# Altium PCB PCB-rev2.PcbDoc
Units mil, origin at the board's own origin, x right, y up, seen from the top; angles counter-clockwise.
Board outline 1995 x 2300 mil, 2 copper layers (Top Layer, Bottom Layer); 24 components, 81 nets, 313 pads, 170 vias.
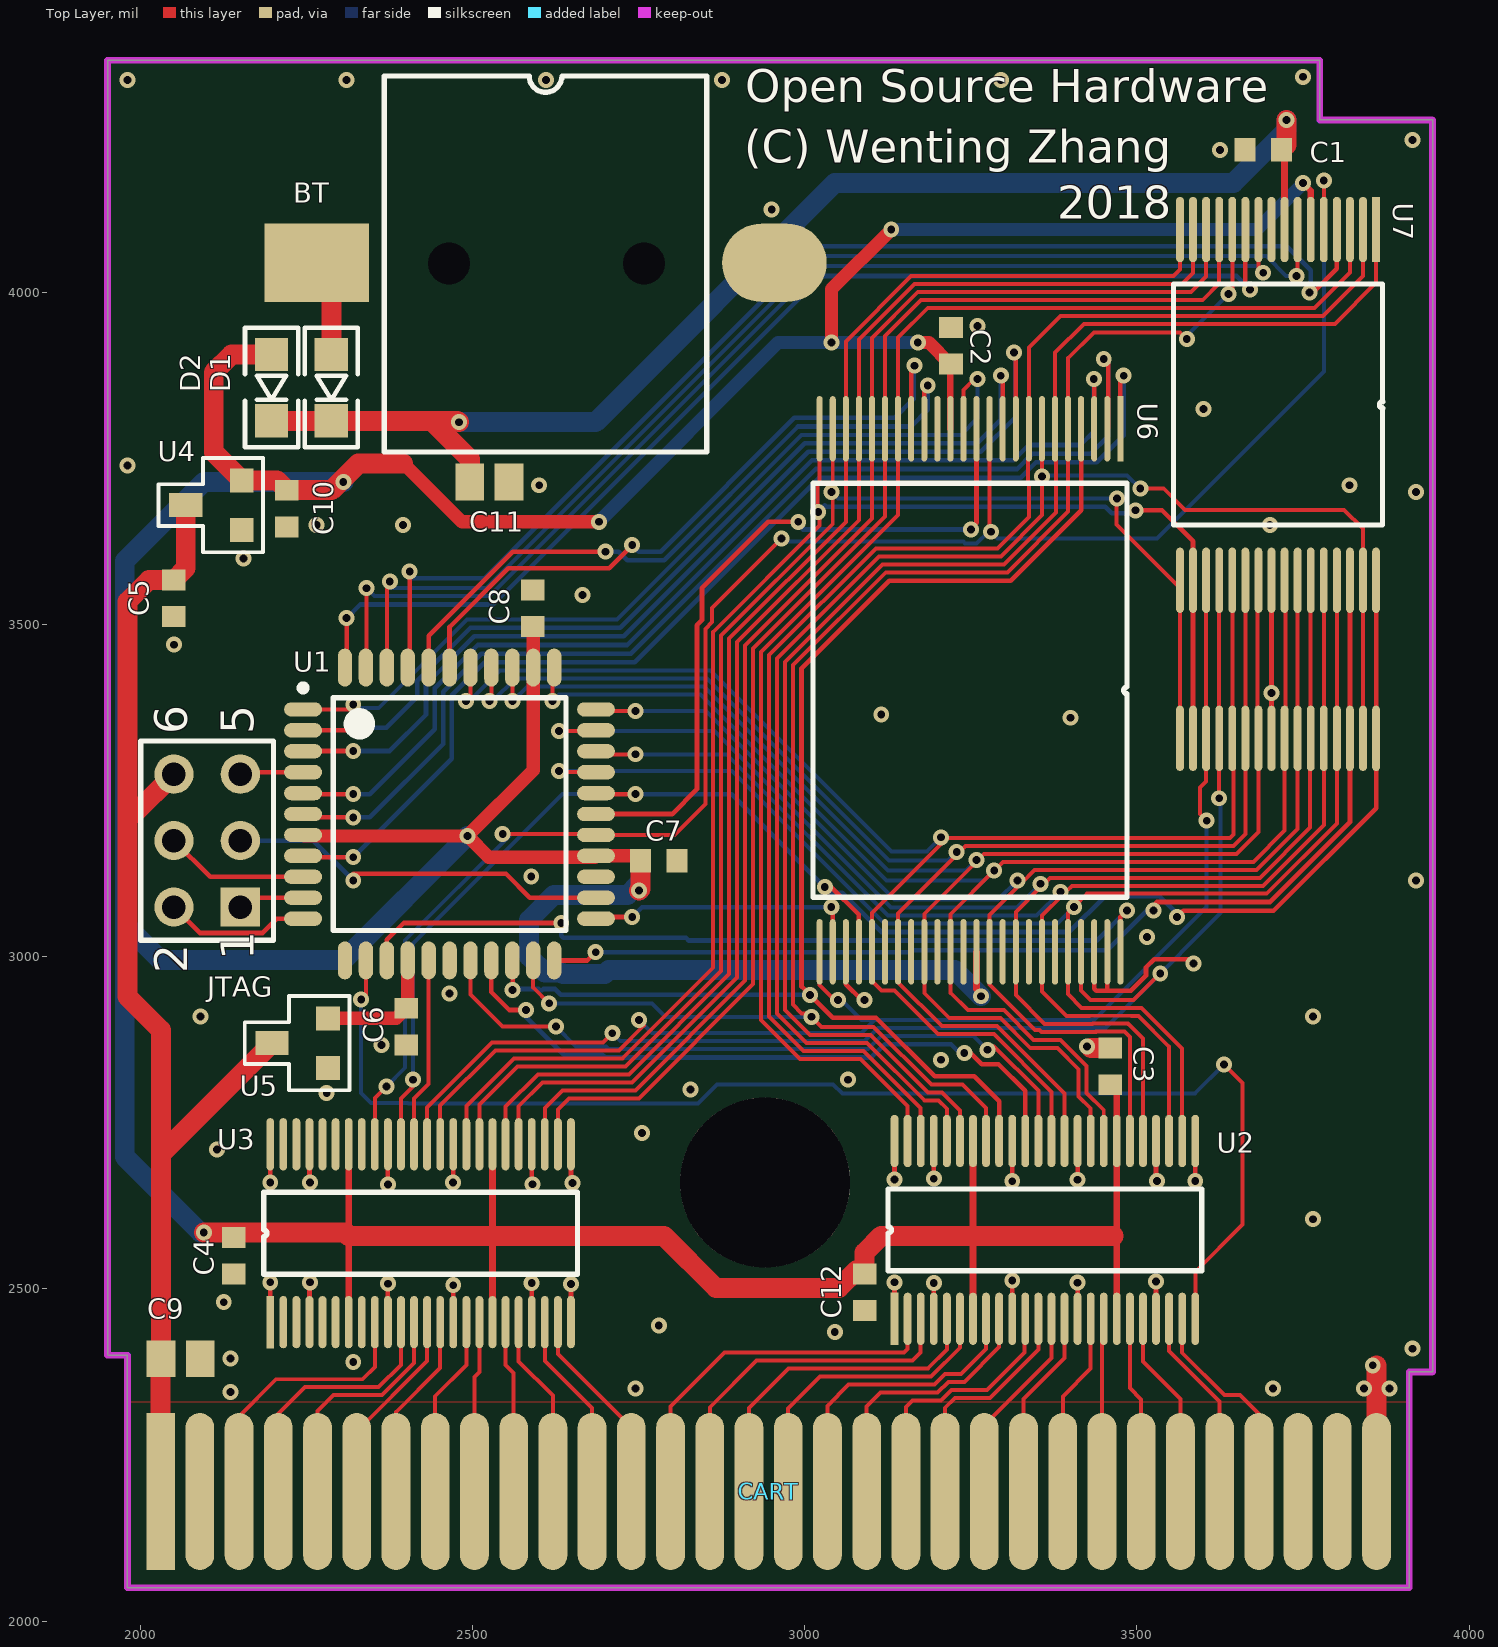
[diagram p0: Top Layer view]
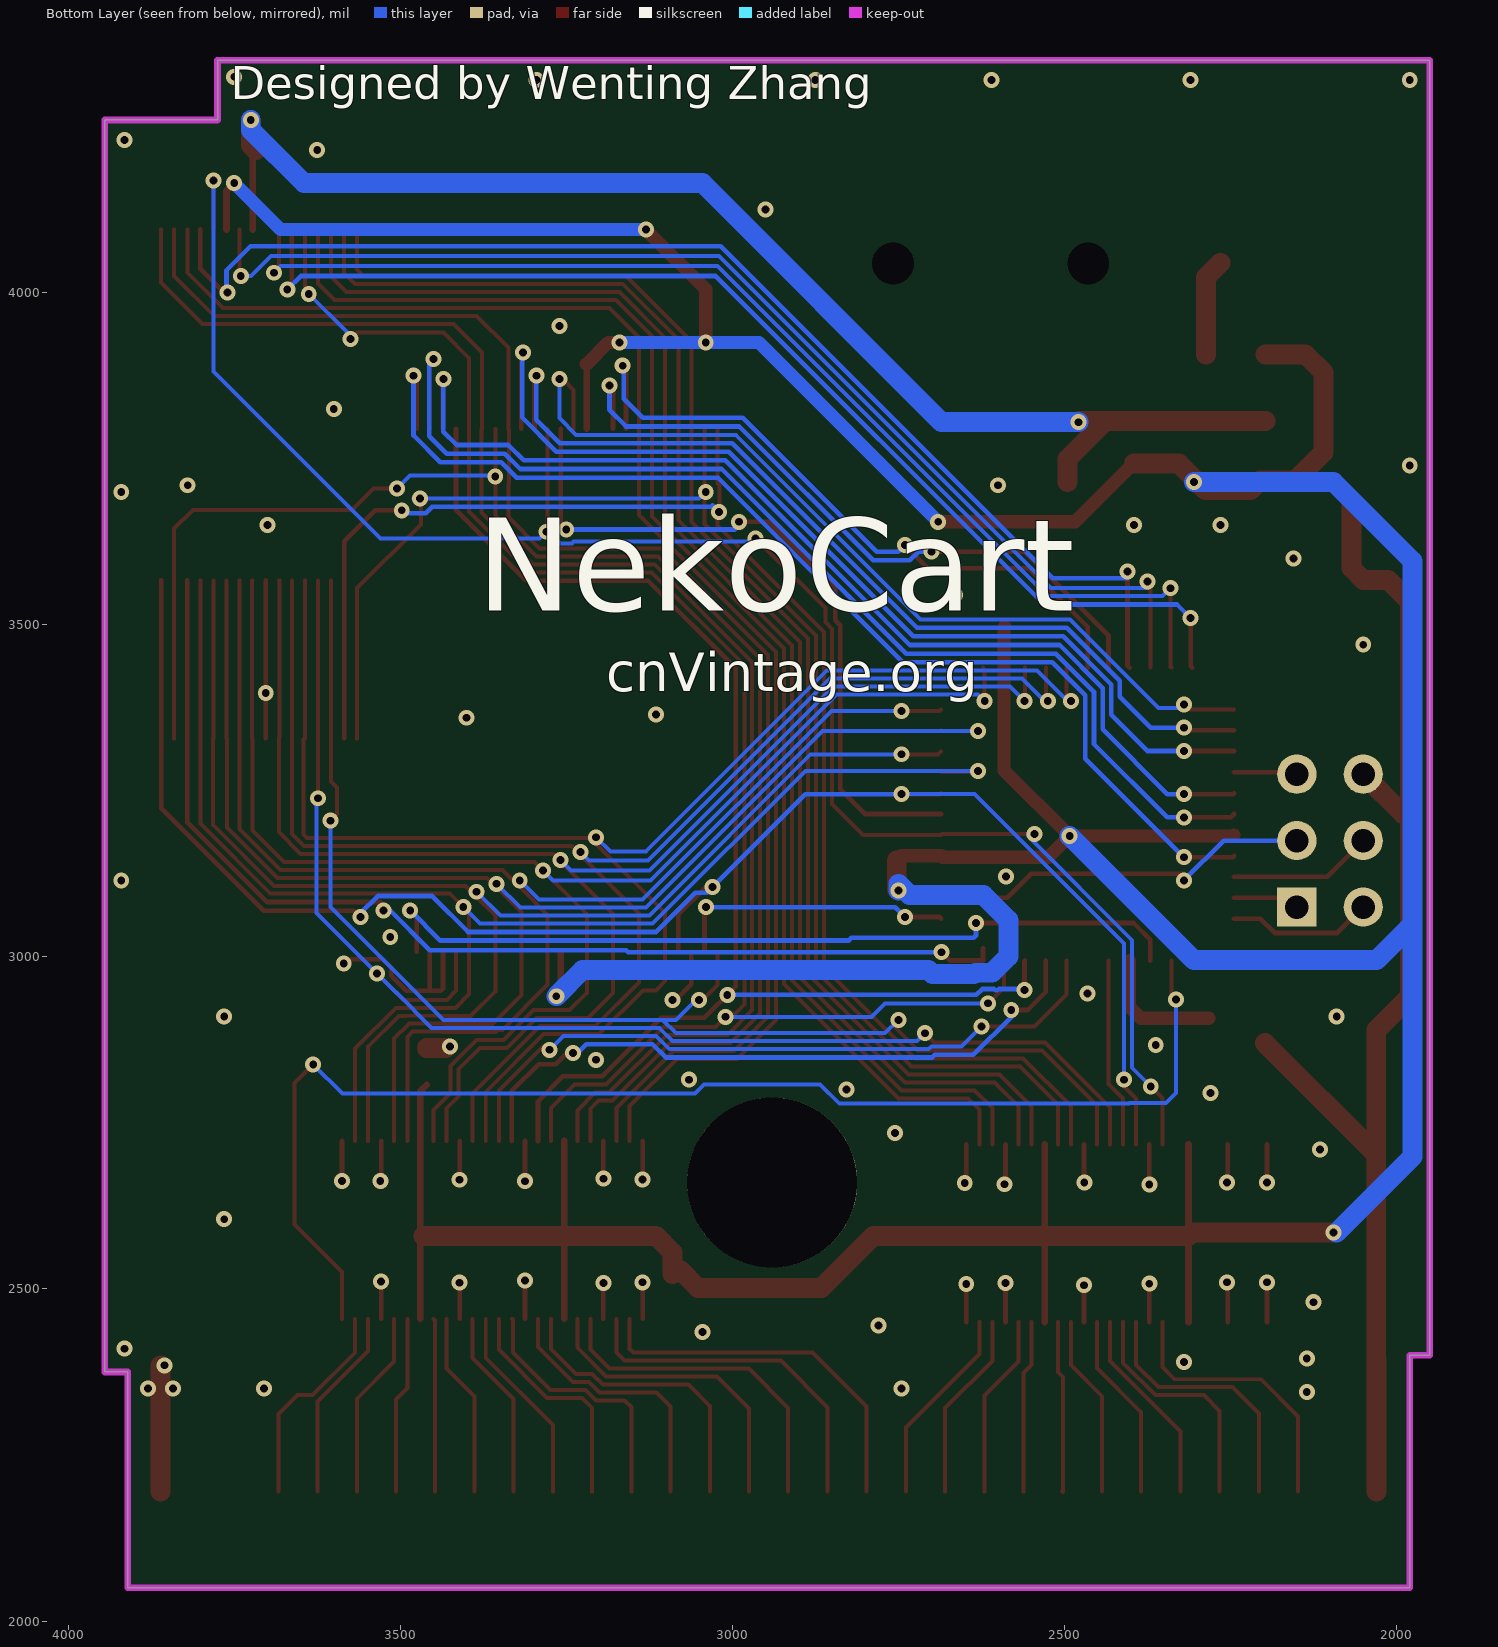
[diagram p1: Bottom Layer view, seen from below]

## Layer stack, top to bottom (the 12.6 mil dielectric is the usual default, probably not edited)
Top Solder: solder mask 0.4, Solder Resist, Dk 3.5
Top Layer: signal copper 1.4
Dielectric 1: dielectric 12.6, FR-4, Dk 4.8
Bottom Layer: signal copper 1.4
Bottom Solder: solder mask 0.4, Solder Resist, Dk 3.5

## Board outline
1980,2050 1980,2400 1950,2400 1950,4350 3775,4350 3775,4260 3945,4260 3945,2375 3910,2375 3910,2050

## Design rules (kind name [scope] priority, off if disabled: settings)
AssemblyTestPointUsage [All] p0: scope1count=1 scope1_0_kind=Board scope1_0_value=Board scope2count=1 scope2_0_kind=Board scope2_0_value=Board commentlength=0
AssemblyTestpoint [All] p0: scope1count=1 scope1_0_kind=Board scope1_0_value=Board scope2count=1 scope2_0_kind=Board scope2_0_value=Board commentlength=0
Clearance [All] p0: scope1count=1 scope1_0_kind=Board scope1_0_value=Board scope2count=1 scope2_0_kind=Board scope2_0_value=Board commentlength=0 gap=6
Clearance [All] p1: gap=6 ignorepadtopadclearanceinfootprint=FALSE except(0: Arc-Hole Track-Hole SMDPad-Hole THPad-Hole Via-Hole Fill-Hole Poly-Hole Region-Hole Text-Hole)
ComponentClearance [All] p0 off: scope1count=1 scope1_0_kind=Board scope1_0_value=Board scope2count=1 scope2_0_kind=Board scope2_0_value=Board commentlength=0 gap=10 collisioncheckmode=3
ComponentClearance [All] p1 off: gap=10 collisioncheckmode=3 verticalgap=10 showdistances=FALSE
DiffPairsRouting [All] p0: scope1count=1 scope1_0_kind=Board scope1_0_value=Board scope2count=1 scope2_0_kind=Board scope2_0_value=Board commentlength=0
FabricationTestPointUsage [All] p0: scope1count=1 scope1_0_kind=Board scope1_0_value=Board scope2count=1 scope2_0_kind=Board scope2_0_value=Board commentlength=0 valid=0 allowmultiple=FALSE
FabricationTestpoint [All] p0: scope1count=1 scope1_0_kind=Board scope1_0_value=Board scope2count=1 scope2_0_kind=Board scope2_0_value=Board commentlength=0 side=3 testpointundercomponent=TRUE minsize=40 maxsize=100 preferedsize=60 minholesize=0 maxholesize=40 preferedholesize=32 testpointgrid=1
FanoutControl Fanout_BGA [All] p0 off: scope1count=1 scope1_0_kind=Board scope1_0_value=Board scope2count=1 scope2_0_kind=Board scope2_0_value=Board commentlength=69 // Protel DXP Scope 1 Expression Was: IsBGA   Fanout_BGA (Default Rule)
FanoutControl Fanout_LCC [All] p0 off: scope1count=1 scope1_0_kind=Board scope1_0_value=Board scope2count=1 scope2_0_kind=Board scope2_0_value=Board commentlength=69 // Protel DXP Scope 1 Expression Was: IsLCC   Fanout_LCC (Default Rule)
FanoutControl Fanout_SOIC [All] p0 off: scope1count=1 scope1_0_kind=Board scope1_0_value=Board scope2count=1 scope2_0_kind=Board scope2_0_value=Board commentlength=71 // Protel DXP Scope 1 Expression Was: IsSOIC   Fanout_SOIC (Default Rule)
FanoutControl Fanout_Small [All] p0 off: scope1count=1 scope1_0_kind=Board scope1_0_value=Board scope2count=1 scope2_0_kind=Board scope2_0_value=Board commentlength=84 // Protel DXP Scope 1 Expression Was: (CompPinCount < 5)   Fanout_Small (Default Rule)
FanoutControl Fanout_Default [All] p0: scope1count=1 scope1_0_kind=Board scope1_0_value=Board scope2count=1 scope2_0_kind=Board scope2_0_value=Board commentlength=30 // Fanout_Default (Default Rule)
Height [All] p0: scope1count=1 scope1_0_kind=Board scope1_0_value=Board scope2count=1 scope2_0_kind=Board scope2_0_value=Board commentlength=0
HoleSize [All] p0: scope1count=1 scope1_0_kind=Board scope1_0_value=Board scope2count=1 scope2_0_kind=Board scope2_0_value=Board commentlength=0 absolutevalues=TRUE maxlimit=400 minlimit=11.81 maxpercent=80.000 minpercent=20.000
HoleSize [All] p1: absolutevalues=TRUE maxlimit=400 minlimit=11.81 maxpercent=80.000 minpercent=20.000
HoleToHoleClearance [All] p0: scope1count=1 scope1_0_kind=Board scope1_0_value=Board scope2count=1 scope2_0_kind=Board scope2_0_value=Board commentlength=0
LayerPairs [All] p0: scope1count=1 scope1_0_kind=Board scope1_0_value=Board scope2count=1 scope2_0_kind=Board scope2_0_value=Board commentlength=0 enforce=TRUE
MinimumSolderMaskSliver [All] p0 off: scope1count=1 scope1_0_kind=Board scope1_0_value=Board scope2count=1 scope2_0_kind=Board scope2_0_value=Board commentlength=0
MinimumSolderMaskSliver [All] p1 off: minsoldermaskwidth=10
NetAntennae [All] p0: scope1count=1 scope1_0_kind=Board scope1_0_value=Board scope2count=1 scope2_0_kind=Board scope2_0_value=Board commentlength=0
PasteMaskExpansion [All] p0: scope1count=1 scope1_0_kind=Board scope1_0_value=Board scope2count=1 scope2_0_kind=Board scope2_0_value=Board commentlength=0 expansion=0
PlaneClearance [All] p0: scope1count=1 scope1_0_kind=Board scope1_0_value=Board scope2count=1 scope2_0_kind=Board scope2_0_value=Board commentlength=0 clearance=20
PlaneConnect [All] p0: scope1count=1 scope1_0_kind=Board scope1_0_value=Board scope2count=1 scope2_0_kind=Board scope2_0_value=Board commentlength=0 planeconnectstyle=Direct reliefexpansion=20 reliefentries=4 reliefconductorwidth=10 reliefairgap=10
PlaneConnect [All] p1: planeconnectstyle=Direct reliefexpansion=20 reliefentries=4 reliefconductorwidth=10 reliefairgap=10
PolygonConnect [All] p0: scope1count=1 scope1_0_kind=Board scope1_0_value=Board scope2count=1 scope2_0_kind=Board scope2_0_value=Board commentlength=0 connectstyle=Relief reliefconductorwidth=10 reliefentries=4 polygonreliefangle="90 Angle"
PolygonConnect PolygonConnect_1 [All] p0 off: scope1count=1 scope1_0_kind=Board scope1_0_value=Board scope2count=1 scope2_0_kind=Board scope2_0_value=Board commentlength=44 connectstyle=Direct reliefconductorwidth=10 reliefentries=4 polygonreliefangle="90 Angle" // Protel DXP Scope 1 Expression Was: IsVia
PolygonConnect PolygonConnect_1 [IsVia] p1: connectstyle=Direct reliefconductorwidth=10 reliefentries=4 polygonreliefangle="90 Angle" airgapwidth=10
PolygonConnect [All] p2: connectstyle=Relief reliefconductorwidth=10 reliefentries=4 polygonreliefangle="90 Angle" airgapwidth=10
RoutingCorners [All] p0: scope1count=1 scope1_0_kind=Board scope1_0_value=Board scope2count=1 scope2_0_kind=Board scope2_0_value=Board commentlength=0 cornerstyle=45-Degree minsetback=100 maxsetback=100
RoutingLayers [All] p0: scope1count=1 scope1_0_kind=Board scope1_0_value=Board scope2count=1 scope2_0_kind=Board scope2_0_value=Board commentlength=0 top layer=Automatic bottom layer=Automatic
RoutingPriority [All] p0: scope1count=1 scope1_0_kind=Board scope1_0_value=Board scope2count=1 scope2_0_kind=Board scope2_0_value=Board commentlength=0
RoutingTopology [All] p0: scope1count=1 scope1_0_kind=Board scope1_0_value=Board scope2count=1 scope2_0_kind=Board scope2_0_value=Board commentlength=0 topology=Shortest
RoutingVias [All] p0: scope1count=1 scope1_0_kind=Board scope1_0_value=Board scope2count=1 scope2_0_kind=Board scope2_0_value=Board commentlength=0 holewidth=11.81 width=24 viastyle="Through Hole" minholewidth=11.81 minwidth=24 maxholewidth=11.81 maxwidth=50
RoutingVias [All] p1: holewidth=11.81 width=24 viastyle="Through Hole" minholewidth=11.81 minwidth=24 maxholewidth=11.81 maxwidth=50
ShortCircuit [All] p0: scope1count=1 scope1_0_kind=Board scope1_0_value=Board scope2count=1 scope2_0_kind=Board scope2_0_value=Board commentlength=0 allowed=FALSE
SilkToBoardRegionClearance [All] p0: scope1count=1 scope1_0_kind=Board scope1_0_value=Board scope2count=1 scope2_0_kind=Board scope2_0_value=Board commentlength=0
SilkToSilkClearance [All] p0: scope1count=1 scope1_0_kind=Board scope1_0_value=Board scope2count=1 scope2_0_kind=Board scope2_0_value=Board commentlength=0
SilkToSilkClearance [All] p1: silktosilkclearance=0
SilkToSolderMaskClearance [All] p0 off: scope1count=1 scope1_0_kind=Board scope1_0_value=Board scope2count=1 scope2_0_kind=Board scope2_0_value=Board commentlength=44 // Protel DXP Scope 1 Expression Was: IsPad
SilkToSolderMaskClearance [IsPad] p1: minsilkscreentomaskgap=0 clearancetoexposedcopper=TRUE
SolderMaskExpansion [All] p0: scope1count=1 scope1_0_kind=Board scope1_0_value=Board scope2count=1 scope2_0_kind=Board scope2_0_value=Board commentlength=0 expansion=4
SolderMaskExpansion [All] p1: expansion=4 istentingtop=FALSE
UnRoutedNet [All] p0: scope1count=1 scope1_0_kind=Board scope1_0_value=Board scope2count=1 scope2_0_kind=Board scope2_0_value=Board commentlength=0
UnpouredPolygon [All] p0: scope1count=1 scope1_0_kind=Board scope1_0_value=Board scope2count=1 scope2_0_kind=Board scope2_0_value=Board commentlength=0
Width [All] p0: scope1count=1 scope1_0_kind=Board scope1_0_value=Board scope2count=1 scope2_0_kind=Board scope2_0_value=Board commentlength=0 maxlimit=30 minlimit=6 preferedwidth=6
Width [All] p1: maxlimit=30 minlimit=6 preferedwidth=6 minimp=50.000000 maximp=50.000000 favimp=50.000000
24 further rules are at their usual default settings.

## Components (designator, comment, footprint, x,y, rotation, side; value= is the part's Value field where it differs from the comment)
BT "CR1220" CR1220 2265,4045 r0 top
C1 "104" 1608[0603] 3690,4215 r0 top
C2 "104" 1608[0603] 3220,3920 r270 top
C3 "104" 1608[0603] 3460,2835 r270 top
C4 "104" 1608[0603] 2140,2550 r90 top
C5 "104" 1608[0603] 2050,3540 r90 top
C6 "104" 1608[0603] 2400,2895 r90 top
C7 "104" 1608[0603] 2780,3145 r180 top
C8 "104" 1608[0603] 2590,3525 r270 top
C9 "106" C0805 2060,2395 r180 top
C10 "104" 1608[0603] 2220,3675 r270 top
C11 "106" C0805 2525,3715 r180 top
C12 "104" 1608[0603] 3090,2495 r90 top
CART "GBCart" GB_CART 2030,2195 r90 top
D1 "MBR0530" 0805D 2335,3880 r270 top
D2 "MBR0530" 0805D 2245,3880 r270 top
JTAG "Header 3X2" HDR2X3 2150,3075 r90 top
U1 "XC2C64A" 44A_L 2465,3215 r0 top
U2 "SN74LVTH162245" TSOP48 3135,2455 r90 top
U3 "SN74LVTH162245" TSOP48 2195,2450 r90 top
U4 "6209" SOT-23 2110,3680 r90 top
U5 "6209" SOT-23 2240,2870 r90 top
U6 "MX29LV640" TSOP48L 3475,3795 r270 top
U7 "IS62LV1024LL" TSOP32 3860,4095 r270 top

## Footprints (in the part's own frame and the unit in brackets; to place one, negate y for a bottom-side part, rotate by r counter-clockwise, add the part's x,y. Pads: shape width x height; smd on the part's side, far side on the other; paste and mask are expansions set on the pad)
44A_L [mm] "44-Pin Thin Quad Flat Pack 0.8 mm Pitch, IPC High Density"
  oval 1.45x0.55 smd: 1(-5.6,4) 2(-5.6,3.2) 3(-5.6,2.4) 4(-5.6,1.6) 5(-5.6,0.8) 6(-5.6,0) 7(-5.6,-0.8) 8(-5.6,-1.6) 9(-5.6,-2.4) 10(-5.6,-3.2) 11(-5.6,-4) 23(5.6,-4) 24(5.6,-3.2) 25(5.6,-2.4) 26(5.6,-1.6) 27(5.6,-0.8) 28(5.6,0) 29(5.6,0.8) 30(5.6,1.6) 31(5.6,2.4) 32(5.6,3.2) 33(5.6,4)
  oval 0.55x1.45 smd: 12(-4,-5.6) 13(-3.2,-5.6) 14(-2.4,-5.6) 15(-1.6,-5.6) 16(-0.8,-5.6) 17(0,-5.6) 18(0.8,-5.6) 19(1.6,-5.6) 20(2.4,-5.6) 21(3.2,-5.6) 22(4,-5.6) 34(4,5.6) 35(3.2,5.6) 36(2.4,5.6) 37(1.6,5.6) 38(0.8,5.6) 39(0,5.6) 40(-0.8,5.6) 41(-1.6,5.6) 42(-2.4,5.6) 43(-3.2,5.6) 44(-4,5.6)
  silkscreen extent -5.72,-4.45 4.45,4.95
0805D [mil]
  rect 50x50 smd: A(-27,-48) K(73,-48)
  silkscreen extent -67,-88 113,-8
1608[0603] [mm] "Chip Capacitor, Body 1.6x0.8mm, IPC High Density"
  rect 0.8x0.9 smd: 1(-0.7,0) 2(0.7,0)
C0805 [mm] "Chip Capacitor, Body 2.0x1.3mm, IPC High Density"
  rect 1.1x1.4 smd: 1(-0.75,0) 2(0.75,0)
CR1220 [mm]
  round 1.5 hole 1.6: 0(5.055,-0.025) 0(12.522,-0.025)
  rect 4x3 smd: 1(0,0)
  oval 4x3 smd: 2(17.5,0)
  silkscreen extent 2.58,-7.24 14.92,7.14
GB_CART [mm]
  rect 6x1.1 smd: 1(0,0)
  oval 6x1.1 smd: 2(0,-1.5) 3(0,-3) 4(0,-4.5) 5(0,-6) 6(0,-7.5) 7(0,-9) 8(0,-10.5) 9(0,-12) 10(0,-13.5) 11(0,-15) 12(0,-16.5) 13(0,-18) 14(0,-19.5) 15(0,-21) 16(0,-22.5) 17(0,-24) 18(0,-25.5) 19(0,-27) 20(0,-28.5) 21(0,-30) 22(0,-31.5) 23(0,-33) 24(0,-34.5) 25(0,-36) 26(0,-37.5) 27(0,-39) 28(0,-40.5) 29(0,-42) 30(0,-43.5) 31(0,-45) 32(0,-46.5)
HDR2X3 [mm] "Connector; Header; 3x2 Position"
  rect 1.5x1.5 hole 0.9: 1(0,0)
  round 1.5 hole 0.9: 2(0,2.54) 3(2.54,0) 4(2.54,2.54) 5(5.08,0) 6(5.08,2.54)
  silkscreen extent -1.27,-1.27 6.35,3.81
SOT-23 [mil]
  rect 36x36 smd: 1(-37.4,-42.18) 2(37.4,-42.18)
  rect 36x50 smd: 3(0,42.18)
  silkscreen extent -71,-74 71,83
TSOP32 [mm]
  rect 2.5x0.3 smd: 1(0,0)
  oval 2.5x0.3 smd: 2(0,-0.5) 3(0,-1) 4(0,-1.5) 5(0,-2) 6(0,-2.5) 7(0,-3) 8(0,-3.5) 9(0,-4) 10(0,-4.5) 11(0,-5) 12(0,-5.5) 13(0,-6) 14(0,-6.5) 15(0,-7) 16(0,-7.5) 17(13.412,-7.5) 17(19.457,-7.5) 18(13.412,-7) 18(19.457,-7) 19(13.412,-6.5) 19(19.457,-6.5) 20(13.412,-6) 20(19.457,-6) 21(13.412,-5.5) 21(19.457,-5.5) 22(13.412,-5) 22(19.457,-5) 23(13.412,-4.5) 23(19.457,-4.5) 24(13.412,-4) 24(19.457,-4) 25(13.412,-3.5) 25(19.457,-3.5) 26(13.412,-3) 26(19.457,-3) 27(13.412,-2.5) 27(19.457,-2.5) 28(13.412,-2) 28(19.457,-2) 29(13.412,-1.5) 29(19.457,-1.5) 30(13.412,-1) 30(19.457,-1) 31(13.412,-0.5) 31(19.457,-0.5) 32(13.412,0) 32(19.457,0)
  silkscreen extent 2.08,-7.75 11.3,0.25
TSOP48 [mm]
  rect 2x0.3 smd: 1(0,0)
  oval 2x0.3 smd: 2(0,-0.5) 3(0,-1) 4(0,-1.5) 5(0,-2) 6(0,-2.5) 7(0,-3) 8(0,-3.5) 9(0,-4) 10(0,-4.5) 11(0,-5) 12(0,-5.5) 13(0,-6) 14(0,-6.5) 15(0,-7) 16(0,-7.5) 17(0,-8) 18(0,-8.5) 19(0,-9) 20(0,-9.5) 21(0,-10) 22(0,-10.5) 23(0,-11) 24(0,-11.5) 25(6.8,-11.5) 26(6.8,-11) 27(6.8,-10.5) 28(6.8,-10) 29(6.8,-9.5) 30(6.8,-9) 31(6.8,-8.5) 32(6.8,-8) 33(6.8,-7.5) 34(6.8,-7) 35(6.8,-6.5) 36(6.8,-6) 37(6.8,-5.5) 38(6.8,-5) 39(6.8,-4.5) 40(6.8,-4) 41(6.8,-3.5) 42(6.8,-3) 43(6.8,-2.5) 44(6.8,-2) 45(6.8,-1.5) 46(6.8,-1) 47(6.8,-0.5) 48(6.8,0)
  silkscreen extent 1.84,-11.75 4.96,0.25
TSOP48L [mm]
  rect 2.5x0.23 smd: 1(0,0)
  oval 2.5x0.23 smd: 2(0,-0.5) 3(0,-1) 4(0,-1.5) 5(0,-2) 6(0,-2.5) 7(0,-3) 8(0,-3.5) 9(0,-4) 10(0,-4.5) 11(0,-5) 12(0,-5.5) 13(0,-6) 14(0,-6.5) 15(0,-7) 16(0,-7.5) 17(0,-8) 18(0,-8.5) 19(0,-9) 20(0,-9.5) 21(0,-10) 22(0,-10.5) 23(0,-11) 24(0,-11.5) 25(20,-11.5) 26(20,-11) 27(20,-10.5) 28(20,-10) 29(20,-9.5) 30(20,-9) 31(20,-8.5) 32(20,-8) 33(20,-7.5) 34(20,-7) 35(20,-6.5) 36(20,-6) 37(20,-5.5) 38(20,-5) 39(20,-4.5) 40(20,-4) 41(20,-3.5) 42(20,-3) 43(20,-2.5) 44(20,-2) 45(20,-1.5) 46(20,-1) 47(20,-0.5) 48(20,0)
  silkscreen extent 2.08,-11.75 17.92,0.25

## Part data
C1 C2 C3 C4 C5 C6 C7 C8 C9 C10 C11 C12: library part "Cap Semi", "Capacitor (Semiconductor SIM Model)"
D1 D2: library part 1N4148
JTAG: "Header, 3-Pin, Dual row"

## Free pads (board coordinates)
  round 255.91 hole 255.91: 0(2940,2660.32)

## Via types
v1: diameter 24.02, hole 11.81, Top Layer to Bottom Layer, tented both sides, 168 vias
v2: diameter 24.02, hole 11.81, Top Layer to Bottom Layer, 2 vias

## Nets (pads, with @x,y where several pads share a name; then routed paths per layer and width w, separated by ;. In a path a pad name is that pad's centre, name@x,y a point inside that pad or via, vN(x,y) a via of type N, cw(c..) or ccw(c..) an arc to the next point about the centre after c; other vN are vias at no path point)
1V8: C6.2 U1.15 U5.2 | length 196.9
  Top Layer w20: U5.2 2384.84,2907.4 C6.2 2402.01,2924.57 U1.15
3V3: C2.2 C3.2 C4.2 C7.2 C8.2 C10.1 C12.2 D2.A U1.7 U1.26 U1.35 U2.7 U2.18 U2.31 U2.42 U3.7 U3.18 U3.31 U3.42 U4.2 U6.14 U6.37 U7.6 | length 9180
  Top Layer w10: U3.7 2313.11,2580 U3.42 ; U3.18 2529.64,2574.64 2535,2580 2529.64,2585.36 U3.31 ; U6.14 3219.09,3891.54 C2.2 ; U2.7 3253.11,2576.89 3250,2580 3253.11,2583.11 U2.42 ; 3258.47,2951.53 U6.37 ; C3.2 3469.64,2797.8 U2.31 3469.64,2584.64 ; 3465,2580 3469.64,2584.64 ; U2.18 3469.64,2584.64 ; v1(3750,4165) 3761.57,4153.43 U7.6
  Top Layer w20: U1.7 2246.04,3181.99 v1(2491.99,3181.99) ; 2395,3742.56 2396.07,3742.56 2483.63,3655 v1(2690,3655) ; C8.2 2590.98,3496.46 U1.35 2590.98,3280.98 v1(2491.99,3181.99) ; C7.2 2745.43,3152.01 U1.26 2683.46,3150 2523.98,3150 v1(2491.99,3181.99) ; v1(3040,3925) 3040,4005 v1(3130,4095) ; v1(3170,3925) 3186.47,3925 3219.03,3892.44 C2.2
  Top Layer w30: v1(2095,2585) 2308.11,2585 2313.11,2580 2535,2580 2787.59,2580 2866.07,2501.52 3051.52,2501.52 C12.2@3078.7,2528.7 ; D2.A 2137,3907 2110,3880 2110,3759.58 U4.2 2205.16,3717.4 C10.1 2287.56,3702.56 2327.56,3742.56 2395,3742.56 ; v1(2750,3100) 2752.44,3102.44 C7.2 ; C12.2 3090,2555 3115,2580 3250,2580 3465,2580
  Bottom Layer w20: v1(2690,3655) 2960,3925 v1(3040,3925) v1(3170,3925) ; v1(3130,4095) 3680,4095 v1(3750,4165)
  Bottom Layer w30: v1@2090,2585 1976,2699 1976,3049 ; v1(2305,3715) 2095,3715 1976,3596 1976,3049 ; v1(2491.99,3181.99) 2305,2995 2030,2995 1976,3049 ; v1(2750,3100) 2750,3110 2733.01,3093.01 2622.01,3093.01 2584.42,3055.42 2584.42,3000.58 2608.99,2976.01 2634.06,2976.01 2636.07,2973.99 2698.67,2973.99 2704.68,2980 3225.65,2980 v1(3265,2940.65)
5V: C5.2 C9.2 CART.1 JTAG.6 U4.3 U5.3 | length 1885.9
  Top Layer w30: 1990,3215 JTAG.6 ; CART.1 2030,2394.53 C9.2 2030.47,2702.65 ; U4.3 2067.82,3585.38 C5.2 2012.56,3567.56 1980,3535 1980,2940 2030.47,2889.53 2030.47,2702.65 ; U5.3 2030.47,2702.65
A0: U3.36 U6.45 U7.20 | length 2083.5
  Top Layer w6: U3.36 2431.22,2773.19 2529.03,2871 2696,2871 v1(2710,2885) ; U6.45 3415.95,2949.05 3429.69,2935.31 3495.02,2935.31 3534.71,2975 v1(3535,2975) ; v1(3623.78,3238.78) 3623.78,3328.97 U7.20@3623.78,3566.97
  Bottom Layer w6: v1(2710,2885) 2722,2873 3089.97,2873 3109.97,2893 3452.71,2893 3505.72,2946.01 3505.72,2945.72 3626.01,3066.01 3626.01,3236.55 v1(3623.78,3238.78)
A1: U3.35 U6.25 U7.19 | length 2030.2
  Top Layer w6: U3.35 2450.91,2775.91 2534,2859 2720.06,2859 2758.03,2896.97 v1(2750,2905) ; U6.25 3022.24,2957.76 3050,2930 v1(3050,2935) ; U7.19@3604.09,3566.97 3604.09,3328.97 3604.09,3264.09 3595,3255 3595,3215 v1(3605,3205)
  Bottom Layer w6: v1(2750,2905) 2770,2885 3085,2885 3105,2905 ; v1(3050,2935) 3055,2935 3085,2905 3105,2905 ; v1(3605,3205) 3605,3075 3435,2905 3105,2905
A2: U3.33 U6.24 U7.18 | length 2286.2
  Top Layer w6: U3.33 2490.28,2775.28 2562,2847 2725.03,2847 2862,2983.97 2862,3488.97 3022.24,3649.22 v1@3022.24,3670 ; v1(3020,3670) 3018.99,3671.01 3018.99,3709.71 3022.24,3712.96 U6.24
  Top Layer w7: v1(3497.71,3672.29) 3537.71,3672.29 3584.41,3625.59 U7.18@3584.41,3328.97
  Bottom Layer w7: v1(3020,3670) 3029.79,3679.79 3032.08,3677.5 3452.08,3677.5 3461.79,3667.79 3493.21,3667.79 v1(3497.71,3672.29)
A3: U3.32 U6.23 U7.17 | length 2264.3
  Top Layer w6: U3.32 2509.96,2777.99 2566.97,2835 2730,2835 2874,2979 2874,3484 3041.93,3651.93 v1@3041.93,3701.93 ; v1(3040,3700) v1@3041.93,3701.93 ; U6.23 v1@3041.93,3701.93 ; v1(3470,3690) 3468.99,3688.99 3468.99,3651.01 3564.72,3555.28 U7.17@3564.72,3328.97
  Bottom Layer w6: v1(3040,3700) 3050,3690 3479.71,3690 3470,3680.29 v1(3470,3690)
A4: U3.30 U6.22 U7.16 | length 2109.7
  Top Layer w6: U3.30 2549.33,2774.33 2598,2823 2734.97,2823 2886,2974.03 2886,3479.03 3061.61,3654.64 U6.22 3061.61,3926.61 3160,4025 3555,4025 3565,4035 3565,4094.72 U7.16
A5: U3.29 U6.21 U7.15 | length 2113
  Top Layer w6: U3.29 2569.01,2775.01 2605,2811 2739.94,2811 2898,2969.06 2898,3474.06 3081.3,3657.36 U6.21 3081.3,3929.33 3164.97,4013 3568,4013 3584.41,4029.41 U7.15
A6: U3.27 U6.20 U7.14 | length 2094.9
  Top Layer w6: U3.27 2608.39,2772.39 2635,2799 2744.91,2799 2910,2964.09 2910,3469.09 3100.99,3660.07 U6.20 3100.99,3932.04 3169.94,4001 3581,4001 3604.09,4024.09 U7.14
A7: U3.26 U6.19 U7.13 | length 2099.6
  Top Layer w6: U3.26 2628.07,2770.07 2645,2787 2749.88,2787 2922,2959.12 2922,3464.12 3120.67,3662.79 U6.19 3120.67,3934.76 3174.91,3989 3599,3989 3623.78,4013.78 U7.13
A8: U2.47 U6.18 U7.3 | length 2225.1
  Top Layer w6: U2.47 3154.68,2775.32 3083.52,2846.48 2992.61,2846.48 2934,2905.09 2934,3459.15 3140.36,3665.5 U6.18 3140.36,3932.36 3185,3977 3767,3977 3820.63,4030.63 U7.3
A9: U2.46 U6.8 U7.2 | length 2230.4
  Top Layer w6: U2.46 3174.37,2772.6 3088.49,2858.48 2997.58,2858.48 2946,2910.06 2946,3454.18 3106.82,3615 3290,3615 3337.2,3662.2 3337.2,3711.76 3335.88,3713.09 3335.88,3793.68 U6.8 3337.2,3917.2 3385,3965 3780,3965 3840.32,4025.32 U7.2
A10: U2.44 U6.7 U7.31 | length 2353.3
  Top Layer w6: U2.44 3213.74,2771.26 3201.5,2783.5 3180.44,2783.5 3093.46,2870.48 3002.55,2870.48 2958,2915.03 2958,3449.21 3111.79,3603 3294.97,3603 3356.89,3664.92 v1(3356.89,3723.11) U6.7 ; v1(3505,3705) 3540.29,3705 3572.29,3673 3812,3673 3840.32,3644.68 3840.32,3566.97 U7.31@3840.32,3328.97
  Bottom Layer w6: v1(3356.89,3723.11) 3355,3725 3485,3725 v1(3505,3705)
A11: U2.43 U6.6 U7.1 | length 2246.2
  Top Layer w6: U2.43 3233.43,2768.55 3206.47,2795.5 3185.41,2795.5 3098.43,2882.48 3007.52,2882.48 2970,2920 2970,3444.24 3116.76,3591 3299.94,3591 3377.9,3668.96 3377.9,3795 U6.6 3376.57,3909.57 3420,3953 3798,3953 3860,4015 U7.1
A12: U1.21 U2.41 U6.5 U7.12 | length 2528.9
  Top Layer w6: U1.21 2590.98,2954.02 v1(2615,2930) ; U2.41 3272.8,2772.2 3237.5,2807.5 3190.38,2807.5 3103.4,2894.48 3025.23,2894.48 v1(3010,2909.71) 3004.71,2915 2995,2915 2982,2928 2982,3439.27 3121.73,3579 3304.91,3579 3396.26,3670.35 U6.5 3396.26,3901.26 3435,3940 3565,3940 v1(3575,3930) ; v1(3637.72,3998.01) 3643.47,4003.76 U7.12
  Top Layer w7: U1.21@2590,2995.51 U1.21
  Bottom Layer w6: v1(2615,2930) 2770,2930 2790.29,2909.71 v1(3010,2909.71) ; v1(3575,3930) 3575,3935 3580,3940 3579.71,3940 v1(3637.72,3998.01)
A13: U1.20 U2.40 U6.4 | length 2048.4
  Top Layer w7: U1.20 2560,2994.02 v1(2560,2950) ; U2.40 3292.48,2782.52 3255,2820 3195.56,2820 3107.06,2908.5 3042.06,2908.5 3020.28,2930.28 3020.01,2930.28 v1(3007.51,2942.79) 2995,2955.29 2995,3434.59 3126.91,3566.5 3310.09,3566.5 3415.95,3672.36 U6.4
  Bottom Layer w7: v1(2560,2950) 2561.51,2951.51 2598.84,2951.51 2600.86,2949.49 2604.08,2949.49 2606.09,2951.51 2623.91,2951.51 2632.63,2942.79 v1(3007.51,2942.79)
A14: U1.19 U2.38 | length 1011.5
  Top Layer w7: U1.19 2527.99,2947.01 2555,2920 v1(2580,2920) ; v1(3240,2855) 3249.58,2855 3266.09,2838.49 3291.51,2838.49 3331.85,2798.15 U2.38
  Bottom Layer w7: v1(2580,2920) 2579.58,2919.58 2579.58,2910 2637.08,2852.5 2695.11,2852.5 2699.11,2848.5 3100.12,2848.5 3120.12,2868.5 3220,2868.5 3233.5,2855 v1(3240,2855)
A15: U1.18 U2.37 | length 1062.6
  Top Layer w6: U1.18 2496.5,2943.5 2545,2895 v1(2625,2895) ; v1(3275,2860) 3280,2865 3285,2865 3351.53,2798.47 U2.37
  Bottom Layer w6: v1(2625,2895) 2655,2865 2700.29,2865 2704.29,2861 3094.94,2861 3114.94,2881 3254,2881 v1(3275,2860)
CS: U1.16 U3.37 | length 285.9
  Top Layer w6: U3.37 2411.53,2786.53 2433.5,2808.5 U1.16
D0: U1.38 U2.36 U6.29 U7.21 | length 2404.1
  Top Layer w6: v1(2490,3385) 2496.5,3391.5 U1.38 ; v1(3205,3180) 3205,3170 3100.99,3065.99 U6.29 3100.99,2963.47 3115.07,2949.39 3134.75,2949.39 3200.5,2883.64 3284.39,2883.64 3371.22,2796.81 U2.36 ; v1@3214,3179 3640.06,3179 3645.53,3184.47 3645.53,3326.9 3643.47,3328.97 U7.21@3643.47,3566.97
  Bottom Layer w6: v1(2490,3385) 2495,3385 2541,3431 2857.79,3431 3130.31,3158.49 3183.49,3158.49 v1(3205,3180) v1@3210,3180
D1: U1.37 U2.35 U6.31 U7.22 | length 2338.8
  Top Layer w6: v1(2525,3385) 2527.99,3387.99 U1.37 ; v1(3228.53,3157.99) 3228.53,3153.53 3140.36,3065.36 U6.31 3140.36,2961.62 3206.33,2895.64 3289.36,2895.64 3390.91,2794.09 U2.35 ; v1@3230.76,3155.76 3242,3167 3645.03,3167 3663.15,3185.12 3663.15,3328.97 U7.22@3663.15,3566.97
  Bottom Layer w6: v1(2525,3385) 2530,3385 2564,3419 2852.82,3419 3126.82,3145 3215.54,3145 v1(3228.53,3157.99)
D2: U1.36 U2.33 U6.33 U7.23 | length 2325.2
  Top Layer w6: U1.36 2559.49,3385.51 v1(2560,3385) ; v1(3258.54,3145.99) v1@3260.99,3145.99 ; v1@3265,3150 v1@3260.99,3145.99 ; 3270,3155 3650,3155 3682.84,3187.84 3682.84,3328.97 3681.47,3330.33 3681.47,3566.97 U7.23@3682.84,3566.97 ; U2.33 3430.28,2772.03 3412.28,2790.03 3412.28,2830.75 3380.03,2863 3339.31,2863 3294.67,2907.64 3217.36,2907.64 3179.72,2945.28 U6.33 3179.72,3064.72 v1@3260.99,3145.99
  Bottom Layer w6: v1(2560,3385) 2582,3407 2847.85,3407 3124.85,3130 3242.55,3130 v1(3258.54,3145.99)
D3: U1.34 U2.32 U6.35 U7.25 | length 2269.5
  Top Layer w6: v1(2620,3385) 2620,3432.99 U1.34 ; U2.32 3449.96,2769.32 3424.28,2795 3424.28,2835.72 3385,2875 3344.28,2875 3299.64,2919.64 3245.36,2919.64 3219.09,2945.91 U6.35 3219.09,3064.09 v1(3285,3130) 3298,3143 3675.12,3143 3722.2,3190.09 3722.2,3328.97 3723.49,3330.25 3723.49,3566.97 U7.25@3722.2,3566.97
  Bottom Layer w6: v1(2620,3385) 2630,3395 2842.88,3395 3122.88,3115 3270,3115 v1(3285,3130)
D4: U1.33 U2.30 U6.38 U7.26 | length 2165.5
  Top Layer w6: U1.33 2687.95,3370 v1(2745,3370) ; v1(3320,3115) 3320,3105 3278.15,3063.15 U6.38 3278.15,2958.1 3346.25,2890 3353.03,2890 3356.03,2887 3438.25,2887 3438.56,2887.31 3481.44,2887.31 3489.33,2879.42 U2.30 ; v1@3325,3110 3346,3131 3680.09,3131 3741.89,3192.8 3741.89,3328.97 U7.26@3741.89,3566.97
  Bottom Layer w6: v1(2745,3370) 2850.91,3370 3134.91,3086 3291,3086 v1(3320,3115)
D5: U1.32 U2.29 U6.40 U7.27 | length 2277.7
  Top Layer w6: v1(2630,3340) 2684.49,3340 U1.32 ; v1(3354.98,3109.99) v1@3354.98,3104.98 ; U2.29 3509.01,2876.99 3487,2899 3486.72,2899 3486.42,2899.31 3433.59,2899.31 3433.28,2899 3361,2899 3317.52,2942.48 U6.40 3317.52,3067.52 v1@3354.98,3104.98 ; U7.27@3761.57,3566.97 3761.57,3328.97 3760.53,3327.92 3760.53,3194.47 3685.06,3119 3369,3119 v1@3354.98,3104.98
  Bottom Layer w6: v1(2630,3340) 2863.94,3340 3129.94,3074 3318.99,3074 v1(3354.98,3109.99)
D6: U1.31 U2.27 U6.42 U7.28 | length 2151.1
  Top Layer w6: U1.31 2689.96,3305 v1(2745,3305) ; v1(3385,3097.99) 3387.01,3100 3395,3100 3402,3107 3690.03,3107 3781.51,3198.49 3781.51,3328.71 3781.26,3328.97 U7.28@3781.26,3566.97 ; v1@3389,3094 3356.89,3061.89 U6.42 3356.89,2948.11 3394,2911 3428.31,2911 3428.61,2911.31 3491.39,2911.31 3491.69,2911 3502.03,2911 3548.39,2864.64 U2.27
  Bottom Layer w6: v1(2745,3305) 2881.97,3305 3124.97,3062 3349.01,3062 v1(3385,3097.99)
D7: U1.30 U2.26 U6.44 U7.29 | length 2230.9
  Top Layer w6: v1(2630,3280) 2632.01,3277.99 U1.30 ; U2.26 3568.07,2861.93 3506.69,2923.31 3416.69,2923.31 3396.26,2943.74 U6.44 3396.26,3066.26 v1(3405,3075) 3425,3095 3695,3095 3800.95,3200.95 3800.95,3328.97 U7.29@3800.95,3566.97
  Bottom Layer w6: v1(2630,3280) 2890,3280 3120,3050 3380,3050 v1(3405,3075)
DDIR: U1.13 U2.24 | length 1968.8
  Top Layer w6: v2(2332,2936) 2333,2936 2339.02,2942.02 U1.13 ; U2.24 3587.76,2525.76 3659,2597 3659,2810 v2(3631,2838)
  Bottom Layer w6: v2(2332,2936) 2332,2795 2347,2780 2402,2780 2403.01,2778.99 2838.99,2778.99 2868,2808 3042.29,2808 3056.3,2793.99 3586.99,2793.99 v2(3631,2838)
GND: BT.2 C1.1 C2.1 C3.1 C4.1 C5.1 C6.1 C7.1 C8.1 C9.1 C10.2 C11.1 C12.1 CART.32 JTAG.5 U1.4 U1.17 U1.25 U2.1 U2.4 U2.10 U2.15 U2.21 U2.25 U2.28 U2.34 U2.39 U2.45 U2.48 U3.1 U3.4 U3.10 U3.15 U3.21 U3.24 U3.25 U3.28 U3.34 U3.39 U3.45 U3.48 U4.1 U5.1 U6.27 U6.46 U6.47 U7.24 | length 2333.5
  Top Layer w7: JTAG.5 2152.99,3277.99 U1.4 ; U3.1 v1(2195,2510) ; v1(2195,2660) U3.48 ; U3.4 2254.05,2509.05 v1(2255,2510) ; U3.45 2254.05,2660.95 v1(2255,2660) ; U3.10 v1(2372.16,2507.84) ; v1(2372.16,2657.16) U3.39 ; v1(2470,2660) 2470.59,2660.59 U3.34 ; U3.15 v1(2470.59,2505.59) ; U3.21 v1(2588.7,2508.7) ; U3.28 2588.7,2656.3 v1(2590,2657.6) ; U3.24 v1(2647.76,2507.24) ; U3.25 2647.76,2657.24 v1(2650,2659.49) ; U6.27 3061.61,2958.8 3085.42,2935 v1(3090,2935) ; U2.1 v1(3135,2510) ; v1(3135,2665) U2.48 ; U2.4 v1(3194.05,2509.05) ; v1(3194.05,2665.95) U2.45 ; U2.10 v1(3312.16,2512.84) ; v1(3312.16,2662.16) U2.39 ; U2.15 v1(3410.59,2509.41) ; v1(3410.59,2664.41) U2.34 ; U6.46 3435.63,2952.18 3438.92,2948.89 3456.74,2948.89 ; U6.47 3455.32,2950.32 3456.74,2948.89 ; U2.21 v1(3528.7,2511.3) ; U2.28 3528.7,2661.3 v1(3530,2662.6) ; v1(3585,2990) 3578.49,2996.51 3526.09,2996.51 3513.49,2983.91 3513.49,2971.46 3490.92,2948.89 3456.74,2948.89 ; v1(3587.76,2662.24) U2.25 ; U7.24@3702.52,3328.97 v1(3702.48,3397.48) U7.24@3702.48,3566.93 ; U7.24@3702.48,3566.93 U7.24@3702.52,3566.97
  Top Layer w30: v1@3430.94,2863 3431.38,2862.56 C3.1 ; CART.32 v1@3860.71,2385
  Bottom Layer w7: v1@2360,2865 v1(2362.44,2867.44) ; v1@2370,2510 v1(2372.16,2507.84) ; v1@2370,2655 v1(2372.16,2657.16) ; v1@2465,2500 v1(2470.59,2505.59) ; v1@2470,2655 v1(2470,2660) ; v1(2588.7,2508.7) v1@2590,2510 ; v1(2590,2657.6) v1@2590,2660 ; v1@2645,2510 v1(2647.76,2507.24) ; v1(2650,2659.49) v1@2650,2660 ; v1(3194.05,2509.05) v1@3195,2510 ; v1(3194.05,2665.95) v1@3195,2665 ; v1@3310,2515 v1(3312.16,2512.84) ; v1@3310,2660 v1(3312.16,2662.16) ; v1@3410,2510 v1(3410.59,2509.41) ; v1@3410,2665 v1(3410.59,2664.41) ; v1(3528.7,2511.3) v1@3530,2510 ; v1(3530,2662.6) v1@3530,2665 ; v1(3587.76,2662.24) v1@3590,2660 ; v1@3700,3395 v1(3702.48,3397.48)
  other v1: 2135,2345 2745,2350 3705,2350 3842,2350 3880,2350 3855,2385 2320,2390 2135,2395 3915,2410 3045,2435 2780,2445 2125,2480 3765,2605 2115,2710 2755,2735 2280,2795 2828,2800 3065,2815 3205,2845 3425,2865 2090,2910 3765,2910 2465,2945 3515,3030 3920,3115 2588,3121 3400,3360 3115,3365 2050,3470 2665,3545 2155,3600 2265,3650 2395,3650 3700,3650 3920,3700 2600,3710 3820,3710 1980,3740 3600,3825 3260,3950 2950,4125 3625,4215 3915,4230 1980,4320 2310,4320 2610,4320 2875,4320 3295,4320 3750,4325
NetBT_1: BT.1 D1.A | length 147.1
  Top Layer w30: BT.1 2287,4023 D1.A
NetC1_2: C1.2 C11.2 D1.K D2.K U7.8 | length 2011.9
  Top Layer w10: C1.2 3722.2,4210.35 U7.8
  Top Layer w30: D2.K D1.K 2438,3807 ; v1(2479,3805) 2477,3807 2438,3807 ; C11.2 2495.47,3749.53 2438,3807 ; C1.2 3725,4222.44 v1(3725,4260)
  Bottom Layer w30: v1(2479,3805) 2685,3805 3045,4165 3645,4165 3725,4245 v1(3725,4260)
NetCART_3: CART.3 U3.9 | length 415.8
  Top Layer w6: CART.3 2148.11,2308.11 2204,2364 2334,2364 2352.48,2382.48 U3.9
NetCART_4: CART.4 U3.11 | length 396.6
  Top Layer w6: CART.4 2207.17,2312.17 2247,2352 2358.06,2352 2391.85,2385.79 U3.11
NetCART_5: CART.5 U3.12 | length 358
  Top Layer w6: CART.5 2266.22,2316.22 2290,2340 2363.03,2340 2411.53,2388.51 U3.12
NetCART_6: CART.6 U3.13 | length 298.9
  Top Layer w6: CART.6 2325.28,2285.28 2431.22,2391.22 U3.13
NetCART_7: CART.7 U3.14 | length 282.6
  Top Layer w6: CART.7 2384.33,2314.33 2450.91,2380.91 U3.14
NetCART_8: CART.8 U3.16 | length 274.4
  Top Layer w6: CART.8 2443.39,2338.39 2490.28,2385.28 U3.16
NetCART_9: CART.9 U3.17 | length 258.6
  Top Layer w6: CART.9 2502.44,2367.44 2509.96,2374.96 U3.17
  Top Layer w7: CART.9 CART.9@2502.78,2195.33
NetCART_10: CART.10 U3.19 | length 260
  Top Layer w6: U3.19 2549.33,2385.67 2561.5,2373.5 CART.10
NetCART_11: CART.11 U3.20 | length 276.3
  Top Layer w6: U3.20 2569.01,2390.99 2620.55,2339.45 CART.11
NetCART_12: CART.12 U3.22 | length 284.5
  Top Layer w6: U3.22 2608.39,2391.61 2679.61,2320.39 CART.12
NetCART_13: CART.13 U3.23 | length 300.8
  Top Layer w6: U3.23 2628.07,2401.93 2738.66,2291.34 CART.13
NetCART_14: CART.14 U2.2 | length 566
  Top Layer w6: CART.14 2797.72,2322.72 2879,2404 3149,2404 3154.68,2409.68 U2.2
NetCART_15: CART.15 U2.3 | length 529.2
  Top Layer w6: CART.15 2856.77,2321.77 2927,2392 3162,2392 3174.37,2404.37 U2.3
NetCART_16: CART.16 U2.5 | length 506.4
  Top Layer w6: CART.16 2915.83,2320.83 2975,2380 3185,2380 3213.74,2408.74 U2.5
NetCART_17: CART.17 U2.6 | length 464.9
  Top Layer w6: CART.17 2974.88,2319.88 3023,2368 3189.97,2368 3233.43,2411.45 U2.6
NetCART_18: CART.18 U2.8 | length 448.6
  Top Layer w6: CART.18 3033.94,2323.94 3066,2356 3194.94,2356 3210.94,2372 3235.03,2372 3272.8,2409.77 U2.8
NetCART_19: CART.19 U2.9 | length 407.1
  Top Layer w6: CART.19 3092.99,2322.99 3114,2344 3199.91,2344 3215.91,2360 3240,2360 3292.48,2412.48 U2.9
NetCART_20: CART.20 U2.11 | length 390.7
  Top Layer w6: CART.20 3152.05,2322.05 3162,2332 3204.88,2332 3220.88,2348 3274.06,2348 3330.53,2404.47 3330.53,2453.68 U2.11
NetCART_21: CART.21 U2.12 | length 349.2
  Top Layer w6: CART.21 3211.1,2321.1 3226,2336 3279.03,2336 3351.53,2408.51 U2.12
NetCART_22: CART.22 U2.13 | length 301.9
  Top Layer w6: CART.22 3270.16,2295.16 3371.22,2396.22 U2.13
NetCART_23: CART.23 U2.14 | length 285.6
  Top Layer w6: CART.23 3329.21,2334.21 3390.91,2395.91 U2.14
NetCART_24: CART.24 U2.16 | length 277.4
  Top Layer w6: CART.24 3388.27,2338.27 3430.28,2380.28 U2.16
NetCART_25: CART.25 U2.17 | length 261.1
  Top Layer w6: CART.25 3447.32,2452.36 U2.17
NetCART_26: CART.26 U2.19 | length 267.1
  Top Layer w6: U2.19 3489.33,2350.67 3506.38,2333.62 CART.26
NetCART_27: CART.27 U2.20 | length 283.4
  Top Layer w6: U2.20 3509.01,2390.99 3565.43,2334.57 CART.27
NetCART_28: CART.28 U2.22 | length 291.5
  Top Layer w6: U2.22 3548.39,2406.61 3624.49,2330.51 CART.28
NetCART_29: CART.29 U2.23 | length 321.3
  Top Layer w6: U2.23 3568.07,2403.9 3631.97,2340 3655,2340 3683.54,2311.46 CART.29
RAM_A13: U1.41 U7.4 | length 1883.8
  Top Layer w7: U1.41 2405,3438.46 v1(2405,3580) ; v1(3760,4000) 3765,4000 3800.95,4035.95 U7.4
  Bottom Layer w7: v1(2405,3580) 2405,3570 2517.67,3570 3017.67,4070 3725.42,4070 3761.51,4033.91 3761.51,4001.51 v1(3760,4000)
RAM_A14: U1.44 U7.11 | length 1750
  Top Layer w7: U1.44 2310,3437.95 v1(2310,3510) ; U7.11 3663.15,4011.85 v1(3670,4005)
  Bottom Layer w7: v1(2310,3510) 2330.5,3530.5 2530.5,3530.5 3025,4025 3650,4025 v1(3670,4005)
RAM_A15: U1.42 U7.7 | length 1796.7
  Top Layer w6: U1.42 2370.51,3560.51 v1(2375,3565) ; v1(3740,4025) 3741.89,4026.89 U7.7
  Bottom Layer w6: v1(2375,3565) 2375,3555 2520.35,3555 3020.35,4055 3694.71,4055 3724.71,4025 v1(3740,4025)
RAM_A16: U1.43 U7.10 | length 1768.2
  Top Layer w6: U1.43 2340,3436.46 v1(2340,3555) ; U7.10 3682.84,4027.16 3687.16,4027.16 v1(3690,4030)
  Bottom Layer w6: v1(2340,3555) 2352,3543 2525.32,3543 3022.32,4040 3680,4040 v1(3690,4030) v1@3685,4025
RAM_CS: U1.22 U7.30 | length 1675.8
  Top Layer w7: U1.22@2622.48,3012.48 U1.22 2672.53,2994.53 v1(2685,3007) ; v1(3525,3070) 3525,3077.5 3530,3082.5 3700.18,3082.5 3820.63,3202.95 3820.63,3328.97 U7.30@3820.63,3566.97
  Bottom Layer w7: v1(2685,3007) 3157,3007 3160,3010 3455.42,3010 3515.42,3070 v1(3525,3070) v1@3525,3075
RD: U1.29 U3.38 U6.28 U7.32 | length 2573.1
  Top Layer w6: U3.38 2391.85,2786.85 2410,2805 v1(2410,2815)
  Top Layer w7: U1.29 2686.97,3245 v1(2745,3245) ; v1(3030,3105) 3040,3105 3081.3,3063.7 U6.28 ; v1(3560,3060) 3569.5,3069.5 3705.56,3069.5 3860,3223.94 3860,3328.97 U7.32@3860,3566.97
  Bottom Layer w6: v1(2410,2815) 2410,3020 2635,3245 v1(2745,3245)
  Bottom Layer w7: v1(2745,3245) 2890,3245 v1(3030,3105) 3038.7,3096.3 3056.02,3096.3 3114.82,3037.5 3397.92,3037.5 3451.92,3091.51 3533.91,3091.51 3560,3065.42 v1(3560,3060)
ROM_A14: U1.5 U6.3 | length 1608.2
  Top Layer w7: U1.5 2246.02,3245 v1(2320,3245) ; v1(3435,3870) 3435.63,3869.37 U6.3
  Bottom Layer w7: v1(2320,3245) 2345,3245 2442.49,3342.49 2442.49,3404.68 2507.31,3469.5 2732.73,3469.5 3010.74,3747.51 3314.1,3747.51 3337.21,3770.62 3415,3770.62 3435,3790.62 v1(3435,3870)
ROM_A15: U1.6 U6.2 | length 1724.8
  Top Layer w7: U1.6 2249.53,3210 v1(2320,3210) ; v1(3450,3900) 3456.51,3893.49 3456.51,3796.19 U6.2
  Bottom Layer w7: v1(2320,3210) 2345,3210 2455.49,3320.49 2455.49,3399.29 2512.7,3456.5 2738.12,3456.5 3016.12,3734.51 3319.49,3734.51 3342.6,3757.62 3430,3757.62 3456.51,3784.13 3456.51,3893.49 v1(3450,3900)
ROM_A16: U1.8 U6.1 | length 1727.3
  Top Layer w7: U1.8 2246.54,3150 v1(2320,3150) ; U6.1 3475,3870 v1(3480,3875)
  Bottom Layer w7: v1(2320,3150) 2468.49,3298.49 2468.49,3393.91 2518.08,3443.5 2743.5,3443.5 3021.51,3721.51 3324.87,3721.51 3347.98,3744.62 3439.62,3744.62 3480,3785 v1(3480,3875)
ROM_A17: U1.14 U6.48 | length 1263.6
  Top Layer w7: U1.14 2370.51,3025.51 2395.95,3050.95 v1(2633.17,3050.95) ; U6.48 3475,3060 v1(3485,3070)
  Bottom Layer w7: v1(2633.17,3050.95) 2633.17,3031.83 2636.49,3028.51 2820.99,3028.51 2825,3024.5 3439.5,3024.5 v1(3485,3070)
ROM_A18: U1.39 U6.17 | length 1068.1
  Top Layer w7: U1.39 2465,3496.62 2553.38,3585 2705.42,3585 2740,3619.58 v1(2740,3620) v1@2745,3615 ; U6.17 3160.04,3889.96 3160,3890 v1(3165,3890)
  Bottom Layer w7: v1(2740,3620) 2750,3610 2782.72,3610 2984.23,3811.51 3135,3811.51 3163.49,3840 3163.49,3888.49 v1(3165,3890)
ROM_A19: U1.40 U6.16 | length 1062.7
  Top Layer w7: U1.40 2433.5,3483.5 2560,3610 v1(2700,3610) ; U6.16 3179.72,3859.72 3180,3860 v1(3185,3860)
  Bottom Layer w7: v1(2700,3610) 2719.58,3610 2732.58,3597 2788.11,3597 2989.61,3798.51 3160,3798.51 3185,3823.51 v1(3185,3860) v1@3180,3860
ROM_A20: U1.3 U6.9 | length 1526.5
  Top Layer w7: U1.3 2245.04,3310 v1(2320,3310) ; v1(3315,3910) 3317.52,3907.52 U6.9
  Bottom Layer w7: v1(2320,3310) 2375,3310 2429.49,3364.49 2429.49,3410.06 2501.93,3482.5 2727.35,3482.5 3005.35,3760.51 3265,3760.51 3316.51,3812.02 3316.51,3908.49 v1(3315,3910) v1@3320,3910
ROM_A21: U1.2 U6.10 | length 1405.6
  Top Layer w7: U1.2 2315.98,3340.98 v1(2320,3345) ; v1(3295,3875) 3297.84,3872.16 U6.10
  Bottom Layer w7: v1(2320,3345) 2370,3345 2416.49,3391.49 2416.49,3415.45 2496.54,3495.5 2721.96,3495.5 2999.97,3773.51 3259.62,3773.51 3295,3808.89 v1(3295,3875)
ROM_A22: U1.1 U6.13 | length 1357
  Top Layer w6: U1.1 2312.48,3372.48 v1(2320,3380) ; U6.13 3238.78,3853.78 3255,3870 v1(3260,3870)
  Bottom Layer w6: v1(2320,3380) 2320,3375 2358.37,3375 2491.37,3508 2716.78,3508 2994.79,3786.01 3235,3786.01 3260,3811.01 v1(3260,3870) v1@3255,3875
ROM_CS: U1.23 U6.26 | length 430.1
  Top Layer w7: U1.23 2687.95,3060 v1(2740,3060) ; v1(3039.79,3074.79) 3040.21,3074.79 3041.93,3073.07 U6.26
  Bottom Layer w7: v1(2740,3060) 2754.79,3074.79 v1(3039.79,3074.79) v1@3040,3075
RST: U1.28 U6.12 | length 1092.5
  Top Layer w7: U1.28 2800,3215 2837.5,3252.5 2837.5,3499.12 2845,3506.62 2845,3555 2945,3655 v1(2990,3655) v1@2995,3650 ; v1(3249.98,3643.49) 3249.98,3644.98 3258.47,3653.47 U6.12
  Bottom Layer w7: v1(2990,3655) 2990,3650 2996.51,3643.49 v1(3249.98,3643.49) v1@3253.08,3643.49
TCK: JTAG.2 U1.11 | length 219.6
  Top Layer w7: JTAG.2 2089.03,3035.97 2183.46,3035.97 2205.01,3057.52 U1.11
TDI: JTAG.4 U1.9 | length 217.1
  Top Layer w7: JTAG.4 2104.49,3120.51 U1.9
TDO: JTAG.3 U1.24 | length 585.2
  Top Layer w7: v1(2320,3115) 2320,3125 2550,3125 2585.98,3089.02 U1.24
  Bottom Layer w7: JTAG.3 2260,3175 v1(2320,3115)
TMS: JTAG.1 U1.10 | length 100.3
  Top Layer w7: JTAG.1 2164.02,3089.02 U1.10
WR: U1.27 U3.40 U6.11 U7.5 | length 2792.6
  Top Layer w6: U3.40 2352.48,2787.48 v1(2370,2805) ; v1(2545,3185) 2683.98,3185 U1.27 2803.5,3183.5 2850,3230 2850,3493.94 2860,3503.94 2860,3525 v1(2965,3630) v1@2970,3625 ; U6.11 3278.15,3641.85 v1(3280,3640) ; U7.5 v1(3781.26,4168.74)
  Bottom Layer w6: v1(2370,2805) 2398,2833 2398,3024.97 2555,3181.97 2555,3185 v1(2545,3185) ; v1(2965,3630) 2970,3625 3238.77,3625 3241.28,3622.48 3258.69,3622.48 3276.2,3640 v1(3280,3640) 3290,3630 3530,3630 3781.26,3881.26 v1(3781.26,4168.74)
pads on no net: BT.0 CART.2 CART.30 CART.31 U1.12 U3.2 U3.3 U3.5 U3.6 U3.8 U3.41 U3.43 U3.44 U3.46 U3.47 U6.15 U6.30 U6.32 U6.34 U6.36 U6.39 U6.41 U6.43 U7.9

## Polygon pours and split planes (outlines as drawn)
GND on Bottom Layer "Bottom Layer-GND" (solid, remove dead copper, pour order 6): 1950,4350 1950,2400 1980,2400 1980,2050 3910,2050 3910,2375 3945,2375 3945,4260 3775,4260 3775,4350
GND on Top Layer "Top Layer-GND" (solid, remove dead copper, pour order 8): 1950,4350 1950,2400 1980,2400 1980,2330 3910,2330 3910,2375 3945,2375 3945,4260 3775,4260 3775,4350

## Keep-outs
Keep-Out Layer:
  the board outline again, w10

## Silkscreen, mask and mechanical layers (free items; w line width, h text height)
Top Overlay:
  text "Open Source Hardware" at 2910,4270 h85
  text "(C) Wenting Zhang" at 2909,4179 h85
  text "2018" at 3380,4095 h85
Bottom Overlay:
  text "Designed by Wenting Zhang" at 3755,4275 h85
  text "Cart" at 2890,3475 h240
  text "Neko" at 3385,3475 h240
  text "cnVintage.org" at 3190,3380 h100
Bottom Paste:
  text "cnVintage.org" at 3305,2105 h60
Bottom Solder:
  text "cnVintage.org" at 3305,2105 h60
